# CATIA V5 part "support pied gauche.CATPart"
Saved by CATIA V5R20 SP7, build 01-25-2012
Part number: support pied gauche
Bounding box of the stored display mesh (mm): x 0.96 to 31.022, y -79 to 36, z 36.159 to 57.621
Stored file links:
  F:\Travaux\Modélisations\CFAO_2011\CFAO_2011_MMS\CFAO_2011_MMS_DONE\CFAO_2011_MMS_jboiteux\Catia\support pied gauche.CATPart
  U:\finthinkmotion\stepper.CATProduct
  F:\Travaux\Modélisations\CFAO_2011\CFAO_2011_MMS\CFAO_2011_MMS_DONE\CFAO_2011_MMS_jboiteux\Catia\roulement 1 pied gauche.CATPart
  F:\Travaux\Modélisations\CFAO_2011\CFAO_2011_MMS\CFAO_2011_MMS_DONE\CFAO_2011_MMS_jboiteux\Catia\bati.CATPart
  F:\Travaux\Modélisations\CFAO_2011\CFAO_2011_MMS\CFAO_2011_MMS_DONE\CFAO_2011_MMS_jboiteux\Catia\part4.CATPart
  F:\Travaux\Modélisations\CFAO_2011\CFAO_2011_MMS\CFAO_2011_MMS_DONE\CFAO_2011_MMS_jboiteux\Catia\Part1.CATPart
  F:\Travaux\Modélisations\CFAO_2011\CFAO_2011_MMS\CFAO_2011_MMS_DONE\CFAO_2011_MMS_jboiteux\Catia\Part35.CATPart
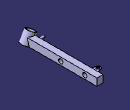
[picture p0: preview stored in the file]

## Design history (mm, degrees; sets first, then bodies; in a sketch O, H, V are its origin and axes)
Parameters
  rayontube = 9 mm {= External.royontubebati}
External parameters (linked from other documents)
  External.royontubebati = 9 mm
Set1
  DatumSurface1: linked copy from another document
  DatumSurface2: linked copy from another document
  Plane1: linked copy from another document
  Point1: linked copy from another document
  Plane2: linked copy from another document
  Plane3: linked copy from another document
  Point2: linked copy from another document
  Line1: linked copy from another document
  Line2: linked copy from another document
Body1 (main body)
  Sketch1 on face of DatumSurface1, origin (-10.9328, 0, 18.9361), H (0, 1, 0), V (0.866, 0, 0.5)
    projected circle E1 centre (-72, 41.4454) radius 7 from edge of DatumSurface1
    projected circle E2 centre (-72, 41.4454) radius 6 from edge of DatumSurface1
  Pad1: profile Sketch1, direction (-0.5, 0, 0.866), up to face of DatumSurface2, offset -2
  Sketch2 on Plane1, origin (0, -72, 0), H (1, 0, 0), V (0, 0, 1)
    line L1 (16.96, 51.121) -> (25.96, 51.121)
    line L2 (25.96, 51.121) -> (25.96, 40.321)
    line L3 (25.96, 40.321) -> (16.96, 40.321)
    line L4 (16.96, 40.321) -> (16.96, 51.121)
    reference projected point E1 (21.46, 45.721) from Point1
    reference projected point E2 (21.46, 45.721) from Point1
    length L3 = 9 {= rayontube}
    length L2 = 10.8 {= rayontube *1.2}
    distance L1 E1 = 5.4 {= rayontube *1.2/2}
    distance L2 E2 = 4.5 {= rayontube /2}
    horizontal: L1 H, L3 H
    vertical: L2 V, L4 V
  Pad2: profile Sketch2, direction (0, 1, 0), up to Plane2, opposite side length -4.5 {= -rayontube /2}
  Sketch3 on end face of Pad1, origin (-19.2828, 0, 33.3987), H (0, -1, 0), V (0.866, 0, 0.5)
    circle A1 centre (72, 41.4454) radius 6
    point P1 (72, 41.4454)
    reference projected point E1 (72, 41.4454) from Point1
    coincidence: E1 P1
  Pocket1: profile Sketch3, direction (0.5, 0, -0.866), through (limit type 6)
  Sketch4 on face of Pad2 from Sketch2.L4, origin (16.96, 0, 0), H (0, -1, 0), V (0, 0, 1)
    circle A1 centre (67.5, 40.321) radius 2.25
    point P1 (67.5, 40.321)
    reference projected point E1 (67.5, 40.321) from vertex [face of Pad2 from Sketch2.L4 | face of Pad2 from Sketch2.L3 | start face of Pad2]
    radius A1 = 2.25 {= rayontube /4}
    coincidence: E1 P1
  Pad3: profile Sketch4, direction (-1, 0, 0), length 9 {= rayontube}
  Sketch5 on end face of Pad3, origin (7.96, 0, 0), H (0, -1, 0), V (0, 0, 1)
    circle A1 centre (67.5, 40.321) radius 1.5
    point P1 (67.5, 40.321)
    reference projected circle E1 centre (67.5, 40.321) radius 2.25 from edge [face of Pad3 from Sketch4.A1 | end face of Pad3]
    radius A1 = 1.5 {= rayontube /6}
    concentricity: E1 P1
  Pad4: profile Sketch5, direction (-1, 0, 0), length 7 {= rayontube /9*7}
  Sketch6 on Plane3, origin (0, 0, 45.721), H (1, 0, 0), V (0, -1, 0)
    projected line E1 (16.96, 65.1031) -> (16.96, -36) from edge [face of Pad2 from Sketch2.L1 | face of Pad2 from Sketch2.L4]
    projected line E2 (16.96, -18.5) -> (16.96, -27.5) from edge [face of Pad2 from Sketch2.L1 | face of Pad2 from Sketch2.L4]
    arc A1 centre (11.46, -23) radius 3.6 from (10.906, -19.4429) to (10.906, -26.5571) ccw
    point P3 (11.46, -23)
    circle A2 centre (11.46, -23) radius 2.4324
    reference projected point E3 (11.46, -23) from Point2
    line L1 (16.96, -18.5) -> (10.906, -19.4429)
    point P4 (16.96, -18.5)
    line L2 (16.96, -27.5) -> (10.906, -26.5571)
    point P6 (16.96, -27.5)
    reference projected line E4 (11.46, -23) -> (21.46, -23) from Line1
    reference projected line E5 (11.46, -23) -> (21.46, -23) from Line1
    radius A1 = 3.6 {= rayontube /2.5}
    radius A2 = 2.4324 {= rayontube /3.7}
    distance E4 P6 = 4.5 {= rayontube /2}
    distance E5 P4 = 4.5 {= rayontube /2}
    coincidence: E3 P3, P4 E1, P6 E1
    tangency: L2 A1, L1 A1
  Pad5: profile Sketch6, direction (0, 0, -1), length 4.5 {= rayontube /2}, opposite side length -3.6 {= -rayontube /2.5}
  Sketch7 on Plane3, origin (0, 0, 45.721), H (1, 0, 0), V (0, -1, 0)
    projected arc E1 centre (11.46, -23) radius 3.6 from (10.906, -19.4429) to (10.906, -26.5571) ccw from edge [start face of Pad5 | face of Pad5 from Sketch6.A1]
    projected line E2 (10.906, -26.5571) -> (16.96, -27.5) from edge [start face of Pad5 | face of Pad5 from Sketch6.L2]
    projected line E3 (16.96, -27.5) -> (16.96, -18.5) from edge [start face of Pad5 | face of Pad2 from Sketch2.L4]
    projected line E4 (16.96, -18.5) -> (10.906, -19.4429) from edge [start face of Pad5 | face of Pad5 from Sketch6.L1]
    projected circle E5 centre (11.46, -23) radius 2.4324 from edge [face of Pad5 from Sketch6.A2 | start face of Pad5]
  Pad6: profile Sketch7, direction (0, 0, 1), length 3.6 {= rayontube /2.5}, opposite side length -4.5 {= -rayontube /2}
  Sketch8 on face of Pad2 from Sketch2.L2, origin (25.96, 0, 0), H (0, 1, 0), V (0, 0, 1)
    circle A1 centre (18, 45.721) radius 3.15
    point P1 (18, 45.721)
    reference projected line E1 (-72, 45.721) -> (36, 45.721) from Line2
    reference intersected line E2 through (36, 0) direction (0, 1) from Plane2
    radius A1 = 3.15 {= rayontube *7/20}
    distance E2 P1 = 18 {= rayontube *2}
    coincidence: E1 P1
  Pocket2: profile Sketch8, direction (-1, 0, 0), length 4.5 {= rayontube /2}
  Sketch9 on face of Pad2 from Sketch2.L2, origin (25.96, 0, 0), H (0, 1, 0), V (0, 0, 1)
    circle A1 centre (-18, 45.721) radius 3.15
    point P1 (-18, 45.721)
    reference projected line E1 (-72, 45.721) -> (36, 45.721) from Line2
    reference intersected line E2 through (36, 0) direction (0, 1) from Plane2
    radius A1 = 3.15 {= rayontube *7/20}
    distance E2 P1 = 54 {= rayontube *6}
    coincidence: E1 P1
  Pocket3: profile Sketch9, direction (-1, 0, 0), length 4.5 {= rayontube /2}
  Sketch10 on end face of Pocket2, origin (21.46, 0, 0), H (0, 1, 0), V (0, 0, 1)
    circle A1 centre (18, 45.721) radius 2.25
    point P1 (18, 45.721)
    circle A2 centre (-18, 45.721) radius 2.25
    point P2 (-18, 45.721)
    reference projected circle E1 centre (-18, 45.721) radius 3.15 from edge [face of Pad2 from Sketch2.L2 | face of Pocket3 from Sketch9.A1]
    reference projected circle E2 centre (18, 45.721) radius 3.15 from edge [face of Pad2 from Sketch2.L2 | face of Pocket2 from Sketch8.A1]
    radius A1 = 2.25 {= rayontube /4}
    radius A2 = 2.25 {= rayontube /4}
    concentricity: E1 P2, E2 P1
  Pocket4: profile Sketch10, direction (1, 0, 0), through (limit type 6)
